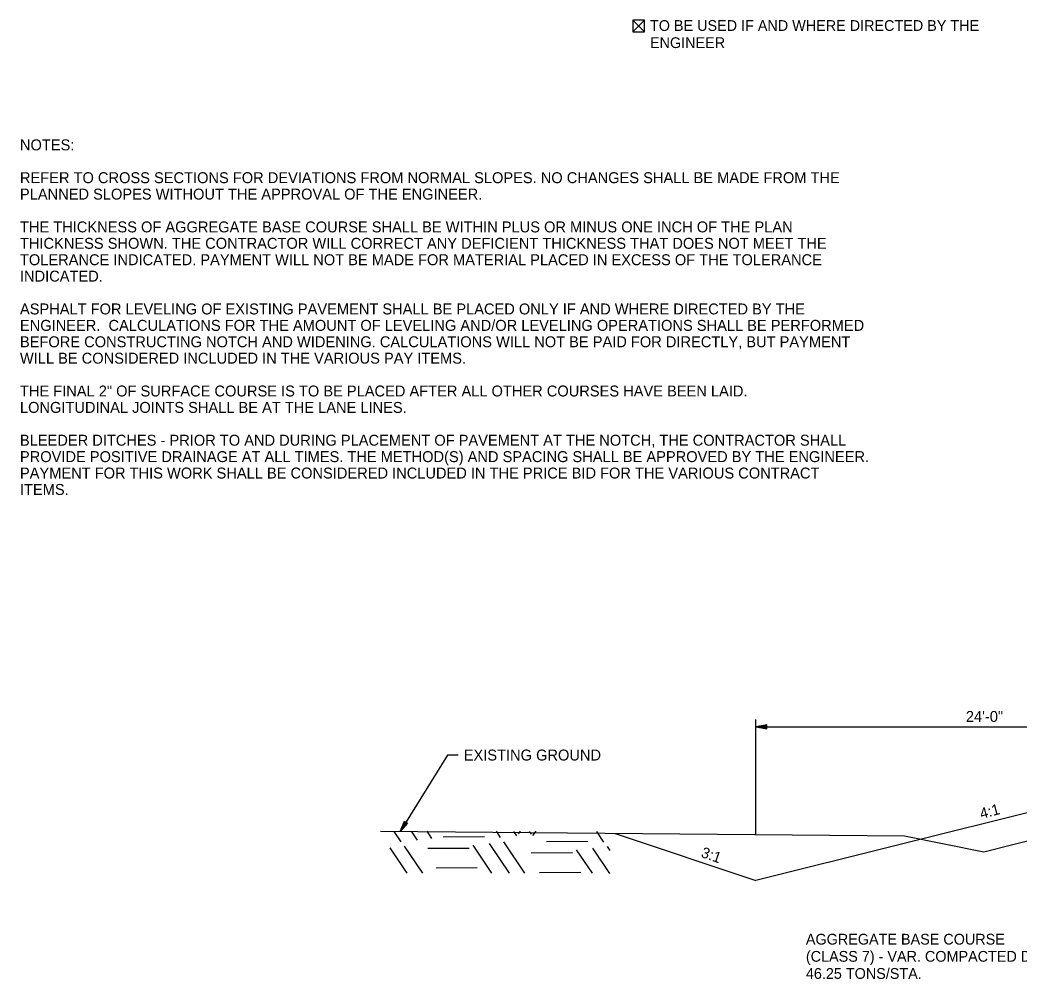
# Model space of a CAD drawing. Extents: x 1461846 to 1462006, y 1686171 to 1686805.
# Drawn here: x 1461850.7 to 1461905.5, y 1686177.8 to 1686230.4 of the extents above; entities that cross this region are included whole.
import ezdxf

# ---------------------------------------------------------------- set-up
doc = ezdxf.new("R2010")
doc.units = 0
for name, color, linetype in [('10', 7, 'Continuous'), ('19', 7, 'Continuous'), ('20', 7, 'Continuous'), ('42', 7, 'Continuous'), ('Level 9', 7, 'Continuous'), ('R_Draft', 7, 'Continuous')]:
    doc.layers.add(name, color=color, linetype=linetype)

msp = doc.modelspace()

# ---------------------------------------------------------------- linework, layer by layer
at = {"layer": '10'}
for p, q in [((1461884.286, 1686230.422), (1461884.928, 1686229.781)), ((1461884.928, 1686230.422), (1461884.286, 1686229.781))]:
    msp.add_line(p, q, dxfattribs=at)
msp.add_lwpolyline([(1461884.679, 1686229.781), (1461884.928, 1686229.781), (1461884.928, 1686230.422), (1461884.286, 1686230.422), (1461884.286, 1686229.781), (1461884.668, 1686229.781)], dxfattribs=at)
at = {"layer": '19'}
for p, q in [((1461891.646, 1686191.774), (1461891.046, 1686191.669)), ((1461891.046, 1686191.669), (1461891.646, 1686191.564)), ((1461891.646, 1686191.719), (1461891.206, 1686191.684)), ((1461891.206, 1686191.654), (1461891.646, 1686191.614)), ((1461891.646, 1686191.564), (1461891.646, 1686191.774)), ((1461911.046, 1686188.239), (1461891.046, 1686183.237)), ((1461910.546, 1686186.547), (1461903.549, 1686184.797)), ((1461899.199, 1686185.676), (1461870.439, 1686185.928)), ((1461871.577, 1686185.355), (1461871.196, 1686185.929)), ((1461872.472, 1686185.447), (1461872.14, 1686185.936)), ((1461873.267, 1686185.539), (1461873.005, 1686185.935)), ((1461877.031, 1686185.595), (1461876.805, 1686185.934)), ((1461877.926, 1686185.687), (1461877.76, 1686185.931)), ((1461878.016, 1686185.793), (1461878.122, 1686185.943)), ((1461878.721, 1686185.779), (1461878.615, 1686185.929)), ((1461878.811, 1686185.7), (1461878.977, 1686185.943)), ((1461882.706, 1686185.345), (1461882.315, 1686185.928)), ((1461876.143, 1686185.624), (1461873.883, 1686185.613)), ((1461881.818, 1686185.384), (1461879.558, 1686185.362)), ((1461883.311, 1686185.815), (1461891.046, 1686183.237)), ((1461903.549, 1686184.797), (1461899.199, 1686185.676)), ((1461871.904, 1686183.64), (1461870.968, 1686185.021)), ((1461872.759, 1686183.637), (1461871.763, 1686185.113)), ((1461875.313, 1686184.996), (1461873.043, 1686184.983)), ((1461876.559, 1686183.636), (1461875.527, 1686185.169)), ((1461877.514, 1686183.634), (1461876.422, 1686185.261)), ((1461878.369, 1686183.632), (1461877.217, 1686185.353)), ((1461882.069, 1686183.63), (1461881.202, 1686184.918)), ((1461883.024, 1686183.628), (1461882.097, 1686185.011)), ((1461883.046, 1686184.877), (1461882.892, 1686185.102)), ((1461880.978, 1686184.755), (1461878.718, 1686184.733)), ((1461875.755, 1686183.926), (1461873.495, 1686183.904)), ((1461881.431, 1686183.675), (1461879.16, 1686183.663))]:
    msp.add_line(p, q, dxfattribs=at)
at = {"layer": '20'}
for p, q in [((1461871.53, 1686185.918), (1461871.753, 1686186.485)), ((1461871.753, 1686186.485), (1461871.931, 1686186.375)), ((1461871.931, 1686186.375), (1461871.53, 1686185.918)), ((1461871.604, 1686186.059), (1461871.796, 1686186.452)), ((1461871.89, 1686186.396), (1461871.626, 1686186.048))]:
    msp.add_line(p, q, dxfattribs=at)
msp.add_lwpolyline([(1461874.712, 1686190.117), (1461874.112, 1686190.117), (1461871.53, 1686185.918)], dxfattribs=at)
at = {"layer": 'Level 9'}
for p, q in [((1461891.046, 1686185.782), (1461891.046, 1686192.072)), ((1461891.046, 1686191.669), (1461915.046, 1686191.669))]:
    msp.add_line(p, q, dxfattribs=at)

# ---------------------------------------------------------------- texts
at = {"layer": '10'}
msp.add_text('EXISTING GROUND', height=0.6, rotation=360, dxfattribs=at).set_placement((1461875.012, 1686189.817))
at = {"layer": '19'}
for s, height, rotation, p in [('TO BE USED IF AND WHERE DIRECTED BY THE', 0.59001, 360, (1461885.231, 1686229.836)), ('ENGINEER', 0.59, 360, (1461885.231, 1686228.896)), ('4:1', 0.59, 14.9782, (1461903.416, 1686186.605)), ('3:1', 0.59, 340.4943, (1461887.984, 1686184.54)), ('AGGREGATE BASE COURSE', 0.59001, 360, (1461893.785, 1686179.721)), ('(CLASS 7) - VAR. COMPACTED DEPTH', 0.59001, 360, (1461893.785, 1686178.781)), ('46.25 TONS/STA.', 0.59001, 360, (1461893.785, 1686177.841))]:
    msp.add_text(s, height=height, rotation=rotation, dxfattribs=at).set_placement(p)
at = {"layer": '42'}
msp.add_text('24\'-0"', height=0.6, dxfattribs=at).set_placement((1461902.562, 1686191.933))
at = {"layer": 'R_Draft'}
for s, p in [('NOTES:', (1461850.662, 1686223.285)), ('REFER TO CROSS SECTIONS FOR DEVIATIONS FROM NORMAL SLOPES. NO CHANGES SHALL BE MADE FROM THE ', (1461850.662, 1686221.485)), ('PLANNED SLOPES WITHOUT THE APPROVAL OF THE ENGINEER.', (1461850.662, 1686220.585)), ('THE THICKNESS OF AGGREGATE BASE COURSE SHALL BE WITHIN PLUS OR MINUS ONE INCH OF THE PLAN ', (1461850.662, 1686218.785)), ('THICKNESS SHOWN. THE CONTRACTOR WILL CORRECT ANY DEFICIENT THICKNESS THAT DOES NOT MEET THE ', (1461850.662, 1686217.885)), ('TOLERANCE INDICATED. PAYMENT WILL NOT BE MADE FOR MATERIAL PLACED IN EXCESS OF THE TOLERANCE ', (1461850.662, 1686216.985)), ('INDICATED.', (1461850.662, 1686216.085)), ('ASPHALT FOR LEVELING OF EXISTING PAVEMENT SHALL BE PLACED ONLY IF AND WHERE DIRECTED BY THE ', (1461850.662, 1686214.285)), ('ENGINEER.  CALCULATIONS FOR THE AMOUNT OF LEVELING AND/OR LEVELING OPERATIONS SHALL BE PERFORMED ', (1461850.662, 1686213.385)), ('BEFORE CONSTRUCTING NOTCH AND WIDENING. CALCULATIONS WILL NOT BE PAID FOR DIRECTLY, BUT PAYMENT ', (1461850.662, 1686212.485)), ('WILL BE CONSIDERED INCLUDED IN THE VARIOUS PAY ITEMS.', (1461850.662, 1686211.585)), ('THE FINAL 2" OF SURFACE COURSE IS TO BE PLACED AFTER ALL OTHER COURSES HAVE BEEN LAID. ', (1461850.662, 1686209.785)), ('LONGITUDINAL JOINTS SHALL BE AT THE LANE LINES.', (1461850.662, 1686208.885)), ('BLEEDER DITCHES - PRIOR TO AND DURING PLACEMENT OF PAVEMENT AT THE NOTCH, THE CONTRACTOR SHALL ', (1461850.662, 1686207.085)), ('PROVIDE POSITIVE DRAINAGE AT ALL TIMES. THE METHOD(S) AND SPACING SHALL BE APPROVED BY THE ENGINEER. ', (1461850.662, 1686206.185)), ('PAYMENT FOR THIS WORK SHALL BE CONSIDERED INCLUDED IN THE PRICE BID FOR THE VARIOUS CONTRACT ', (1461850.662, 1686205.285)), ('ITEMS.', (1461850.662, 1686204.385))]:
    msp.add_text(s, height=0.6, dxfattribs=at).set_placement(p)

doc.saveas('drawing.dxf')
